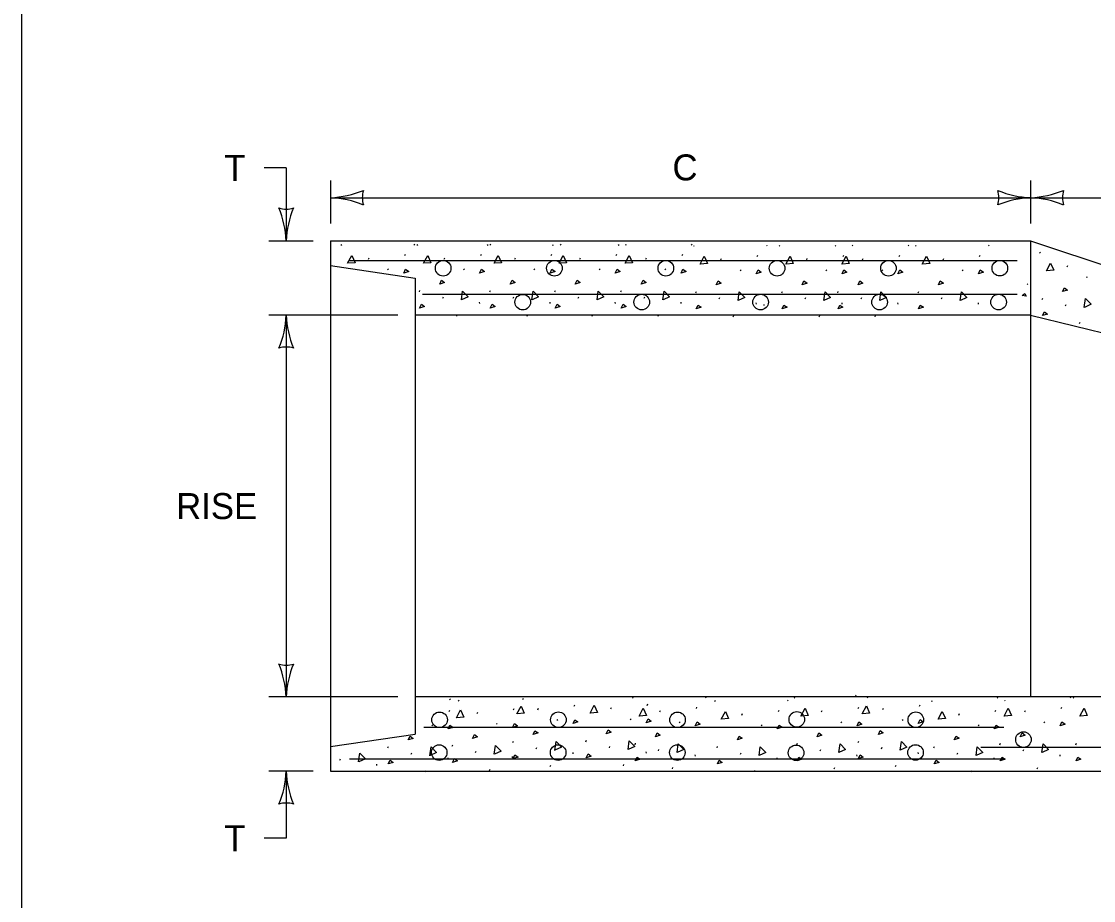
# Model space of a CAD drawing. Extents: x 49991.4 to 50021, y 49987.6 to 50011.4.
# Drawn here: x 50000.336 to 50002.813, y 50004.765 to 50006.796 of the extents above; entities that cross this region are included whole.
import ezdxf

# ---------------------------------------------------------------- set-up
doc = ezdxf.new("R2010")
doc.units = 0
for name, color, linetype in [('Level 1', 7, 'Continuous'), ('Level 2', 7, 'Continuous'), ('Level 3', 7, 'Continuous')]:
    doc.layers.add(name, color=color, linetype=linetype)

msp = doc.modelspace()

# ---------------------------------------------------------------- linework, layer by layer
at = {"layer": 'Level 1'}
for p, q in [((50001.0497, 50006.2887), (50002.6674, 50006.2887)), ((50001.0497, 50006.2887), (50001.0497, 50005.0634)), ((50001.0737, 50006.2801), (50001.0751, 50006.278)), ((50001.2424, 50006.2809), (50001.2438, 50006.2788)), ((50001.249, 50006.2801), (50001.2504, 50006.278)), ((50001.4119, 50006.2801), (50001.4133, 50006.278)), ((50001.4177, 50006.2809), (50001.4191, 50006.2788)), ((50001.5623, 50006.2801), (50001.5637, 50006.278)), ((50001.5806, 50006.2809), (50001.582, 50006.2788)), ((50001.7146, 50006.2801), (50001.716, 50006.278)), ((50001.731, 50006.2809), (50001.7324, 50006.2788)), ((50001.8833, 50006.2809), (50001.8847, 50006.2788)), ((50001.8881, 50006.2783), (50001.8895, 50006.2762)), ((50002.0568, 50006.2791), (50002.0582, 50006.277)), ((50002.0864, 50006.2783), (50002.0878, 50006.2762)), ((50002.2156, 50006.2783), (50002.217, 50006.2762)), ((50002.2551, 50006.2791), (50002.2565, 50006.277)), ((50002.3843, 50006.2791), (50002.3857, 50006.277)), ((50002.4015, 50006.2783), (50002.4029, 50006.2762)), ((50002.5702, 50006.2791), (50002.5716, 50006.277)), ((50002.6674, 50006.2887), (50004.4205, 50005.7044)), ((50002.6674, 50006.2887), (50002.6674, 50005.2346)), ((50002.6674, 50006.2887), (50002.6674, 50005.2346)), ((50002.6674, 50006.2887), (50002.6674, 50005.2346)), ((50001.2214, 50006.2546), (50001.2229, 50006.2578)), ((50001.3967, 50006.2546), (50001.3982, 50006.2578)), ((50001.5596, 50006.2546), (50001.5611, 50006.2578)), ((50001.71, 50006.2546), (50001.7115, 50006.2578)), ((50001.8623, 50006.2546), (50001.8638, 50006.2578)), ((50002.0358, 50006.2528), (50002.0373, 50006.256)), ((50002.2341, 50006.2528), (50002.2356, 50006.256)), ((50002.3633, 50006.2528), (50002.3648, 50006.256)), ((50002.5492, 50006.2528), (50002.5507, 50006.256)), ((50002.6882, 50006.2626), (50002.6896, 50006.2605)), ((50001.0497, 50006.2316), (50001.2456, 50006.2028)), ((50001.1372, 50006.2464), (50001.1387, 50006.2496)), ((50001.3125, 50006.2464), (50001.314, 50006.2496)), ((50001.4754, 50006.2464), (50001.4769, 50006.2496)), ((50001.6258, 50006.2464), (50001.6273, 50006.2496)), ((50001.7781, 50006.2464), (50001.7796, 50006.2496)), ((50001.9516, 50006.2446), (50001.9531, 50006.2478)), ((50002.1499, 50006.2446), (50002.1514, 50006.2478)), ((50002.2791, 50006.2446), (50002.2806, 50006.2478)), ((50002.465, 50006.2446), (50002.4665, 50006.2478)), ((50002.7517, 50006.2289), (50002.7532, 50006.2321)), ((50001.1816, 50006.2237), (50001.1831, 50006.2215)), ((50001.2456, 50006.2028), (50001.2456, 50005.1493)), ((50001.3569, 50006.2237), (50001.3584, 50006.2215)), ((50001.5198, 50006.2237), (50001.5213, 50006.2215)), ((50001.6702, 50006.2237), (50001.6717, 50006.2215)), ((50001.8225, 50006.2237), (50001.824, 50006.2215)), ((50001.996, 50006.2219), (50001.9975, 50006.2197)), ((50002.1943, 50006.2219), (50002.1958, 50006.2197)), ((50002.3235, 50006.2219), (50002.325, 50006.2197)), ((50002.5094, 50006.2219), (50002.5109, 50006.2197)), ((50002.7961, 50006.2062), (50002.7976, 50006.204)), ((50002.6592, 50006.188), (50002.6612, 50006.1898)), ((50001.255, 50006.1707), (50001.2564, 50006.1739)), ((50001.309, 50006.1562), (50001.3104, 50006.1594)), ((50001.4179, 50006.1707), (50001.4193, 50006.1739)), ((50001.4719, 50006.1562), (50001.4733, 50006.1594)), ((50001.5683, 50006.1707), (50001.5697, 50006.1739)), ((50001.6223, 50006.1562), (50001.6237, 50006.1594)), ((50001.7206, 50006.1707), (50001.722, 50006.1739)), ((50001.7746, 50006.1562), (50001.776, 50006.1594)), ((50001.8941, 50006.1689), (50001.8955, 50006.1721)), ((50001.9481, 50006.1544), (50001.9495, 50006.1576)), ((50002.0924, 50006.1689), (50002.0938, 50006.1721)), ((50002.1464, 50006.1544), (50002.1478, 50006.1576)), ((50002.2216, 50006.1689), (50002.223, 50006.1721)), ((50002.2756, 50006.1544), (50002.277, 50006.1576)), ((50002.4075, 50006.1689), (50002.4089, 50006.1721)), ((50002.4615, 50006.1544), (50002.4629, 50006.1576)), ((50002.6942, 50006.1532), (50002.6956, 50006.1564)), ((50001.3934, 50006.1473), (50001.3938, 50006.1441)), ((50001.5563, 50006.1473), (50001.5567, 50006.1441)), ((50001.7067, 50006.1473), (50001.7071, 50006.1441)), ((50001.859, 50006.1473), (50001.8594, 50006.1441)), ((50002.0325, 50006.1455), (50002.0329, 50006.1423)), ((50002.0527, 50006.1401), (50002.0499, 50006.1401)), ((50002.2308, 50006.1455), (50002.2312, 50006.1423)), ((50002.36, 50006.1455), (50002.3604, 50006.1423)), ((50002.5459, 50006.1455), (50002.5463, 50006.1423)), ((50002.7482, 50006.1387), (50002.7496, 50006.1419)), ((50002.6674, 50006.1169), (50001.2456, 50006.1169)), ((50001.3413, 50006.115), (50001.3427, 50006.1182)), ((50001.5042, 50006.115), (50001.5056, 50006.1182)), ((50001.6546, 50006.115), (50001.656, 50006.1182)), ((50001.8069, 50006.115), (50001.8083, 50006.1182)), ((50001.9804, 50006.1132), (50001.9818, 50006.1164)), ((50002.1787, 50006.1132), (50002.1801, 50006.1164)), ((50002.3079, 50006.1132), (50002.3093, 50006.1164)), ((50002.6674, 50006.1169), (50004.481, 50005.6755)), ((50002.7805, 50006.0975), (50002.7819, 50006.1007)), ((50002.2627, 50005.2394), (50002.2641, 50005.2373)), ((50004.5792, 50005.2351), (50001.2456, 50005.2351)), ((50001.325, 50005.2304), (50001.3264, 50005.2283)), ((50001.3449, 50005.2277), (50001.3463, 50005.2256)), ((50001.4937, 50005.2312), (50001.4951, 50005.2291)), ((50001.6126, 50005.2138), (50001.6141, 50005.217)), ((50001.7473, 50005.2341), (50001.7487, 50005.232)), ((50001.7817, 50005.2156), (50001.7832, 50005.2188)), ((50001.895, 50005.2086), (50001.8965, 50005.2118)), ((50001.916, 50005.2349), (50001.9174, 50005.2328)), ((50001.9368, 50005.227), (50001.9382, 50005.2249)), ((50002.1055, 50005.2278), (50002.1069, 50005.2257)), ((50002.121, 50005.2341), (50002.1224, 50005.232)), ((50002.2687, 50005.2086), (50002.2702, 50005.2118)), ((50002.2897, 50005.2349), (50002.2911, 50005.2328)), ((50002.4104, 50005.2139), (50002.4119, 50005.2171)), ((50002.438, 50005.227), (50002.4394, 50005.2249)), ((50002.5903, 50005.2341), (50002.5917, 50005.232)), ((50002.6067, 50005.2278), (50002.6081, 50005.2257)), ((50002.738, 50005.2086), (50002.7395, 50005.2118)), ((50002.759, 50005.2349), (50002.7604, 50005.2328)), ((50002.7656, 50005.2341), (50002.767, 50005.232)), ((50001.3239, 50005.2014), (50001.3254, 50005.2046)), ((50001.3885, 50005.1967), (50001.39, 50005.1999)), ((50001.4727, 50005.2049), (50001.4742, 50005.2081)), ((50001.5284, 50005.2056), (50001.5299, 50005.2088)), ((50001.6975, 50005.2074), (50001.699, 50005.2106)), ((50001.8108, 50005.2004), (50001.8123, 50005.2036)), ((50002.0003, 50005.1933), (50002.0018, 50005.1965)), ((50002.0845, 50005.2015), (50002.086, 50005.2047)), ((50002.1845, 50005.2004), (50002.186, 50005.2036)), ((50002.3262, 50005.2057), (50002.3277, 50005.2089)), ((50002.5015, 50005.1933), (50002.503, 50005.1965)), ((50002.5857, 50005.2015), (50002.5872, 50005.2047)), ((50002.6538, 50005.2004), (50002.6553, 50005.2036)), ((50001.2841, 50005.1705), (50001.2856, 50005.1683)), ((50001.4329, 50005.174), (50001.4344, 50005.1718)), ((50001.5728, 50005.1829), (50001.5743, 50005.1807)), ((50001.7419, 50005.1847), (50001.7434, 50005.1825)), ((50001.8552, 50005.1777), (50001.8567, 50005.1755)), ((50002.0447, 50005.1706), (50002.0462, 50005.1684)), ((50002.2289, 50005.1777), (50002.2304, 50005.1755)), ((50002.3706, 50005.183), (50002.3721, 50005.1808)), ((50002.5459, 50005.1706), (50002.5474, 50005.1684)), ((50002.6982, 50005.1777), (50002.6997, 50005.1755)), ((50001.0497, 50005.1204), (50001.2456, 50005.1493)), ((50001.1822, 50005.1175), (50001.1836, 50005.1207)), ((50001.331, 50005.121), (50001.3324, 50005.1242)), ((50001.4709, 50005.1299), (50001.4723, 50005.1331)), ((50001.5249, 50005.1154), (50001.5263, 50005.1186)), ((50001.64, 50005.1317), (50001.6414, 50005.1349)), ((50001.694, 50005.1172), (50001.6954, 50005.1204)), ((50001.7533, 50005.1247), (50001.7547, 50005.1279)), ((50001.8073, 50005.1102), (50001.8087, 50005.1134)), ((50001.9428, 50005.1176), (50001.9442, 50005.1208)), ((50002.127, 50005.1247), (50002.1284, 50005.1279)), ((50002.181, 50005.1102), (50002.1824, 50005.1134)), ((50002.2687, 50005.13), (50002.2701, 50005.1332)), ((50002.3227, 50005.1155), (50002.3241, 50005.1187)), ((50002.444, 50005.1176), (50002.4454, 50005.1208)), ((50002.5963, 50005.1247), (50002.5977, 50005.1279)), ((50002.6503, 50005.1102), (50002.6517, 50005.1134)), ((50002.7716, 50005.1247), (50002.773, 50005.1279)), ((50001.0715, 50005.0889), (50001.0729, 50005.0921)), ((50001.2362, 50005.103), (50001.2376, 50005.1062)), ((50001.3206, 50005.0941), (50001.321, 50005.0909)), ((50001.385, 50005.1065), (50001.3864, 50005.1097)), ((50001.4694, 50005.0976), (50001.4698, 50005.0944)), ((50001.6093, 50005.1065), (50001.6097, 50005.1033)), ((50001.7784, 50005.1083), (50001.7788, 50005.1051)), ((50001.8917, 50005.1013), (50001.8921, 50005.0981)), ((50001.9968, 50005.1031), (50001.9982, 50005.1063)), ((50002.0812, 50005.0942), (50002.0816, 50005.091)), ((50002.2654, 50005.1013), (50002.2658, 50005.0981)), ((50002.4071, 50005.1066), (50002.4075, 50005.1034)), ((50002.498, 50005.1031), (50002.4994, 50005.1063)), ((50002.5824, 50005.0942), (50002.5828, 50005.091)), ((50002.7347, 50005.1013), (50002.7351, 50005.0981)), ((50001.0497, 50005.0634), (50004.5792, 50005.0634)), ((50001.1559, 50005.08), (50001.1563, 50005.0768)), ((50001.2685, 50005.0618), (50001.2699, 50005.065)), ((50001.4173, 50005.0653), (50001.4187, 50005.0685)), ((50001.5572, 50005.0742), (50001.5586, 50005.0774)), ((50001.7263, 50005.076), (50001.7277, 50005.0792)), ((50001.8396, 50005.069), (50001.841, 50005.0722)), ((50002.0291, 50005.0619), (50002.0305, 50005.0651)), ((50002.2133, 50005.069), (50002.2147, 50005.0722)), ((50002.355, 50005.0743), (50002.3564, 50005.0775)), ((50002.5303, 50005.0619), (50002.5317, 50005.0651)), ((50002.6826, 50005.069), (50002.684, 50005.0722))]:
    msp.add_line(p, q, dxfattribs=at)
msp.add_lwpolyline([(50008.6146, 50011.2628), (50000.3356, 50011.2628), (50000.3356, 50000.0624), (50008.6146, 50000.0624)], close=True, dxfattribs=at)
for points in [[(50001.0893, 50006.2368), (50001.0989, 50006.2549), (50001.1063, 50006.2382), (50001.0896, 50006.2368)], [(50001.2646, 50006.2368), (50001.2742, 50006.2549), (50001.2816, 50006.2382), (50001.265, 50006.2368)], [(50001.4275, 50006.2368), (50001.4371, 50006.2549), (50001.4445, 50006.2382), (50001.4278, 50006.2368)], [(50001.5779, 50006.2368), (50001.5875, 50006.2549), (50001.5949, 50006.2382), (50001.5782, 50006.2368)], [(50001.7302, 50006.2368), (50001.7398, 50006.2549), (50001.7472, 50006.2382), (50001.7306, 50006.2368)], [(50001.9037, 50006.235), (50001.9133, 50006.2531), (50001.9207, 50006.2364), (50001.904, 50006.235)], [(50002.102, 50006.235), (50002.1116, 50006.2531), (50002.119, 50006.2364), (50002.1024, 50006.235)], [(50002.2312, 50006.235), (50002.2408, 50006.2531), (50002.2482, 50006.2364), (50002.2316, 50006.235)], [(50002.4171, 50006.235), (50002.4267, 50006.2531), (50002.4341, 50006.2364), (50002.4174, 50006.235)], [(50001.0933, 50006.2437), (50002.6363, 50006.2437)], [(50002.7038, 50006.2193), (50002.7134, 50006.2374), (50002.7208, 50006.2207), (50002.7042, 50006.2193)], [(50001.2189, 50006.2144), (50001.2232, 50006.2233), (50001.2303, 50006.218), (50001.2189, 50006.2144)], [(50001.3942, 50006.2144), (50001.3985, 50006.2233), (50001.4056, 50006.218), (50001.3942, 50006.2144)], [(50001.5571, 50006.2144), (50001.5614, 50006.2233), (50001.5685, 50006.218), (50001.5571, 50006.2144)], [(50001.7075, 50006.2144), (50001.7118, 50006.2233), (50001.7189, 50006.218), (50001.7075, 50006.2144)], [(50001.8598, 50006.2144), (50001.8641, 50006.2233), (50001.8712, 50006.218), (50001.8598, 50006.2144)], [(50002.0333, 50006.2126), (50002.0376, 50006.2215), (50002.0447, 50006.2162), (50002.0333, 50006.2126)], [(50002.2316, 50006.2126), (50002.2359, 50006.2215), (50002.243, 50006.2162), (50002.2316, 50006.2126)], [(50002.3608, 50006.2126), (50002.3651, 50006.2215), (50002.3722, 50006.2162), (50002.3608, 50006.2126)], [(50002.5467, 50006.2126), (50002.551, 50006.2215), (50002.5581, 50006.2162), (50002.5467, 50006.2126)], [(50001.302, 50006.189), (50001.3062, 50006.1979), (50001.3133, 50006.1926), (50001.302, 50006.189)], [(50001.4649, 50006.189), (50001.4691, 50006.1979), (50001.4762, 50006.1926), (50001.4649, 50006.189)], [(50001.6153, 50006.189), (50001.6195, 50006.1979), (50001.6266, 50006.1926), (50001.6153, 50006.189)], [(50001.7676, 50006.189), (50001.7718, 50006.1979), (50001.7789, 50006.1926), (50001.7676, 50006.189)], [(50001.9411, 50006.1872), (50001.9453, 50006.1961), (50001.9524, 50006.1908), (50001.9411, 50006.1872)], [(50002.1394, 50006.1872), (50002.1436, 50006.1961), (50002.1507, 50006.1908), (50002.1394, 50006.1872)], [(50002.2686, 50006.1872), (50002.2728, 50006.1961), (50002.2799, 50006.1908), (50002.2686, 50006.1872)], [(50002.4545, 50006.1872), (50002.4587, 50006.1961), (50002.4658, 50006.1908), (50002.4545, 50006.1872)], [(50002.7412, 50006.1715), (50002.7454, 50006.1804), (50002.7525, 50006.1751), (50002.7412, 50006.1715)], [(50001.2624, 50006.1652), (50002.6363, 50006.1652)], [(50001.3522, 50006.1525), (50001.355, 50006.1728), (50001.3677, 50006.1597), (50001.3525, 50006.1526)], [(50001.5151, 50006.1525), (50001.5179, 50006.1728), (50001.5306, 50006.1597), (50001.5154, 50006.1526)], [(50001.6655, 50006.1525), (50001.6683, 50006.1728), (50001.681, 50006.1597), (50001.6658, 50006.1526)], [(50001.8178, 50006.1525), (50001.8206, 50006.1728), (50001.8333, 50006.1597), (50001.8181, 50006.1526)], [(50001.9913, 50006.1507), (50001.9941, 50006.171), (50002.0068, 50006.1579), (50001.9916, 50006.1508)], [(50002.1896, 50006.1507), (50002.1924, 50006.171), (50002.2051, 50006.1579), (50002.1899, 50006.1508)], [(50002.3188, 50006.1507), (50002.3216, 50006.171), (50002.3343, 50006.1579), (50002.3191, 50006.1508)], [(50002.5047, 50006.1507), (50002.5075, 50006.171), (50002.5202, 50006.1579), (50002.505, 50006.1508)], [(50002.6479, 50006.1625), (50002.6536, 50006.1671), (50002.6567, 50006.1613), (50002.6479, 50006.1625)], [(50002.7914, 50006.135), (50002.7942, 50006.1553), (50002.8069, 50006.1422), (50002.7917, 50006.1351)], [(50001.2557, 50006.1334), (50001.26, 50006.1423), (50001.2671, 50006.137), (50001.2557, 50006.1334)], [(50001.4186, 50006.1334), (50001.4229, 50006.1423), (50001.43, 50006.137), (50001.4186, 50006.1334)], [(50001.569, 50006.1334), (50001.5733, 50006.1423), (50001.5804, 50006.137), (50001.569, 50006.1334)], [(50001.7213, 50006.1334), (50001.7256, 50006.1423), (50001.7327, 50006.137), (50001.7213, 50006.1334)], [(50001.8948, 50006.1316), (50001.8991, 50006.1405), (50001.9062, 50006.1352), (50001.8948, 50006.1316)], [(50002.0931, 50006.1316), (50002.0974, 50006.1405), (50002.1045, 50006.1352), (50002.0931, 50006.1316)], [(50002.2223, 50006.1316), (50002.2266, 50006.1405), (50002.2337, 50006.1352), (50002.2223, 50006.1316)], [(50002.4082, 50006.1316), (50002.4125, 50006.1405), (50002.4196, 50006.1352), (50002.4082, 50006.1316)], [(50002.6949, 50006.1159), (50002.6992, 50006.1248), (50002.7063, 50006.1195), (50002.6949, 50006.1159)], [(50001.4805, 50005.196), (50001.4901, 50005.2141), (50001.4975, 50005.1974), (50001.4808, 50005.196)], [(50001.6496, 50005.1978), (50001.6592, 50005.2159), (50001.6666, 50005.1992), (50001.65, 50005.1978)], [(50002.2783, 50005.1961), (50002.2879, 50005.2142), (50002.2953, 50005.1975), (50002.2786, 50005.1961)], [(50001.3406, 50005.1871), (50001.3502, 50005.2052), (50001.3576, 50005.1885), (50001.341, 50005.1871)], [(50001.7629, 50005.1908), (50001.7725, 50005.2089), (50001.7799, 50005.1922), (50001.7632, 50005.1908)], [(50001.9524, 50005.1837), (50001.962, 50005.2018), (50001.9694, 50005.1851), (50001.9528, 50005.1837)], [(50002.1366, 50005.1908), (50002.1462, 50005.2089), (50002.1536, 50005.1922), (50002.137, 50005.1908)], [(50002.4536, 50005.1837), (50002.4632, 50005.2018), (50002.4706, 50005.1851), (50002.454, 50005.1837)], [(50002.6059, 50005.1908), (50002.6155, 50005.2089), (50002.6229, 50005.1922), (50002.6062, 50005.1908)], [(50002.7812, 50005.1908), (50002.7908, 50005.2089), (50002.7982, 50005.1922), (50002.7816, 50005.1908)], [(50002.6053, 50005.1642), (50001.2657, 50005.1642)], [(50001.3214, 50005.1612), (50001.3257, 50005.1701), (50001.3328, 50005.1648), (50001.3214, 50005.1612)], [(50001.4702, 50005.1647), (50001.4745, 50005.1736), (50001.4816, 50005.1683), (50001.4702, 50005.1647)], [(50001.6101, 50005.1736), (50001.6144, 50005.1825), (50001.6215, 50005.1772), (50001.6101, 50005.1736)], [(50001.7792, 50005.1754), (50001.7835, 50005.1843), (50001.7906, 50005.179), (50001.7792, 50005.1754)], [(50001.8925, 50005.1684), (50001.8968, 50005.1773), (50001.9039, 50005.172), (50001.8925, 50005.1684)], [(50002.082, 50005.1613), (50002.0863, 50005.1702), (50002.0934, 50005.1649), (50002.082, 50005.1613)], [(50002.2662, 50005.1684), (50002.2705, 50005.1773), (50002.2776, 50005.172), (50002.2662, 50005.1684)], [(50002.4079, 50005.1737), (50002.4122, 50005.1826), (50002.4193, 50005.1773), (50002.4079, 50005.1737)], [(50002.5832, 50005.1613), (50002.5875, 50005.1702), (50002.5946, 50005.1649), (50002.5832, 50005.1613)], [(50002.7355, 50005.1684), (50002.7398, 50005.1773), (50002.7469, 50005.172), (50002.7355, 50005.1684)], [(50001.2292, 50005.1358), (50001.2334, 50005.1447), (50001.2405, 50005.1394), (50001.2292, 50005.1358)], [(50001.378, 50005.1393), (50001.3822, 50005.1482), (50001.3893, 50005.1429), (50001.378, 50005.1393)], [(50001.5179, 50005.1482), (50001.5221, 50005.1571), (50001.5292, 50005.1518), (50001.5179, 50005.1482)], [(50001.687, 50005.15), (50001.6912, 50005.1589), (50001.6983, 50005.1536), (50001.687, 50005.15)], [(50001.8003, 50005.143), (50001.8045, 50005.1519), (50001.8116, 50005.1466), (50001.8003, 50005.143)], [(50001.9898, 50005.1359), (50001.994, 50005.1448), (50002.0011, 50005.1395), (50001.9898, 50005.1359)], [(50002.174, 50005.143), (50002.1782, 50005.1519), (50002.1853, 50005.1466), (50002.174, 50005.143)], [(50002.3157, 50005.1483), (50002.3199, 50005.1572), (50002.327, 50005.1519), (50002.3157, 50005.1483)], [(50002.491, 50005.1359), (50002.4952, 50005.1448), (50002.5023, 50005.1395), (50002.491, 50005.1359)], [(50002.6433, 50005.143), (50002.6475, 50005.1519), (50002.6546, 50005.1466), (50002.6433, 50005.143)], [(50001.2794, 50005.0993), (50001.2822, 50005.1196), (50001.2949, 50005.1065), (50001.2797, 50005.0994)], [(50001.4282, 50005.1028), (50001.431, 50005.1231), (50001.4437, 50005.11), (50001.4285, 50005.1029)], [(50001.5681, 50005.1117), (50001.5709, 50005.132), (50001.5836, 50005.1189), (50001.5684, 50005.1118)], [(50001.7372, 50005.1135), (50001.74, 50005.1338), (50001.7527, 50005.1207), (50001.7375, 50005.1136)], [(50001.8505, 50005.1065), (50001.8533, 50005.1268), (50001.866, 50005.1137), (50001.8508, 50005.1066)], [(50002.04, 50005.0994), (50002.0428, 50005.1197), (50002.0555, 50005.1066), (50002.0403, 50005.0995)], [(50002.2242, 50005.1065), (50002.227, 50005.1268), (50002.2397, 50005.1137), (50002.2245, 50005.1066)], [(50002.3659, 50005.1118), (50002.3687, 50005.1321), (50002.3814, 50005.119), (50002.3662, 50005.1119)], [(50002.5412, 50005.0994), (50002.544, 50005.1197), (50002.5567, 50005.1066), (50002.5415, 50005.0995)], [(50004.5336, 50005.1185), (50002.5522, 50005.1185)], [(50002.6935, 50005.1065), (50002.6963, 50005.1268), (50002.709, 50005.1137), (50002.6938, 50005.1066)], [(50002.6053, 50005.0912), (50001.0933, 50005.0912)], [(50001.1147, 50005.0852), (50001.1175, 50005.1055), (50001.1302, 50005.0924), (50001.115, 50005.0853)], [(50001.1829, 50005.0802), (50001.1872, 50005.0891), (50001.1943, 50005.0838), (50001.1829, 50005.0802)], [(50001.3317, 50005.0837), (50001.336, 50005.0926), (50001.3431, 50005.0873), (50001.3317, 50005.0837)], [(50001.4716, 50005.0926), (50001.4759, 50005.1015), (50001.483, 50005.0962), (50001.4716, 50005.0926)], [(50001.6407, 50005.0944), (50001.645, 50005.1033), (50001.6521, 50005.098), (50001.6407, 50005.0944)], [(50001.754, 50005.0874), (50001.7583, 50005.0963), (50001.7654, 50005.091), (50001.754, 50005.0874)], [(50001.9435, 50005.0803), (50001.9478, 50005.0892), (50001.9549, 50005.0839), (50001.9435, 50005.0803)], [(50002.1277, 50005.0874), (50002.132, 50005.0963), (50002.1391, 50005.091), (50002.1277, 50005.0874)], [(50002.2694, 50005.0927), (50002.2737, 50005.1016), (50002.2808, 50005.0963), (50002.2694, 50005.0927)], [(50002.4447, 50005.0803), (50002.449, 50005.0892), (50002.4561, 50005.0839), (50002.4447, 50005.0803)], [(50002.597, 50005.0874), (50002.6013, 50005.0963), (50002.6084, 50005.091), (50002.597, 50005.0874)], [(50002.7723, 50005.0874), (50002.7766, 50005.0963), (50002.7837, 50005.091), (50002.7723, 50005.0874)]]:
    msp.add_lwpolyline(points, dxfattribs=at)
for centre in [(50001.31, 50006.2255), (50001.567, 50006.2255), (50001.8245, 50006.2254), (50002.0815, 50006.2254), (50002.3389, 50006.2254), (50002.5962, 50006.2256), (50001.4939, 50006.1471), (50001.7688, 50006.1472), (50002.0434, 50006.1472), (50002.3183, 50006.1472), (50002.5933, 50006.1472), (50001.3017, 50005.1822), (50001.5763, 50005.1824), (50001.8515, 50005.1822), (50002.1271, 50005.1831), (50002.4021, 50005.1824), (50002.6508, 50005.1365), (50001.3008, 50005.1066), (50001.5757, 50005.1066), (50001.8511, 50005.1066), (50002.1254, 50005.106), (50002.4014, 50005.1068)]:
    msp.add_circle(centre, 0.018, dxfattribs=at)
at = {"layer": 'Level 3'}
for p, q in [((50000.9474, 50006.4572), (50000.8964, 50006.4572)), ((50000.9474, 50006.4572), (50000.9474, 50006.2887)), ((50001.0497, 50006.4284), (50001.0497, 50006.3287)), ((50002.6674, 50006.4284), (50002.6674, 50006.3287)), ((50001.0497, 50006.3884), (50002.6674, 50006.3884)), ((50002.6674, 50006.3884), (50004.5792, 50006.3884)), ((50000.9074, 50006.2887), (50001.0097, 50006.2887)), ((50001.2056, 50006.1169), (50000.9074, 50006.1169)), ((50000.9474, 50006.1169), (50000.9474, 50005.2351)), ((50001.2056, 50005.2351), (50000.9074, 50005.2351)), ((50001.0097, 50005.0634), (50000.9074, 50005.0634)), ((50000.9474, 50005.0634), (50000.9474, 50004.9087)), ((50000.9474, 50004.9087), (50000.8964, 50004.9087))]:
    msp.add_line(p, q, dxfattribs=at)
for centre, radius, start, end in [((50001.0382, 50006.6211), 0.233, 272.8273, 292.0772), ((50001.1779, 50006.3884), 0.0548, 162.1388, 197.8612), ((50002.6766, 50006.6105), 0.2223, 247.456, 267.6395), ((50002.5392, 50006.3884), 0.0548, 342.1388, 17.8612), ((50002.6559, 50006.6211), 0.233, 272.8273, 292.0772), ((50002.7956, 50006.3884), 0.0548, 162.1388, 197.8612), ((50001.0406, 50006.1662), 0.2223, 67.456, 87.6395), ((50002.6789, 50006.1557), 0.233, 92.8273, 112.0772), ((50002.6583, 50006.1662), 0.2223, 67.456, 87.6395), ((50000.9474, 50006.4169), 0.0548, 252.1388, 287.8612), ((50000.7147, 50006.2772), 0.233, 2.8273, 22.0772), ((50001.1696, 50006.2795), 0.2223, 157.456, 177.6395), ((50000.7253, 50006.126), 0.2223, 337.456, 357.6395), ((50001.1801, 50006.1284), 0.233, 182.8273, 202.0772), ((50000.9474, 50005.9887), 0.0548, 72.1388, 107.8612), ((50000.9474, 50005.3633), 0.0548, 252.1388, 287.8612), ((50000.7147, 50005.2236), 0.233, 2.8273, 22.0772), ((50001.1696, 50005.2259), 0.2223, 157.456, 177.6395), ((50000.7253, 50005.0725), 0.2223, 337.456, 357.6395), ((50001.1801, 50005.0749), 0.233, 182.8273, 202.0772), ((50000.9474, 50004.9352), 0.0548, 72.1388, 107.8612)]:
    msp.add_arc(centre, radius, start, end, dxfattribs=at)

# ---------------------------------------------------------------- texts
at = {"layer": 'Level 2'}
for s, p in [('T', (50000.8044, 50006.4272)), ('C', (50001.8398, 50006.4284)), ('RISE', (50000.693, 50005.646)), ('T', (50000.8044, 50004.8787))]:
    msp.add_text(s, height=0.06, dxfattribs=at).set_placement(p)

doc.saveas('drawing.dxf')
